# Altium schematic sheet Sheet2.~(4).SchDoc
size A3
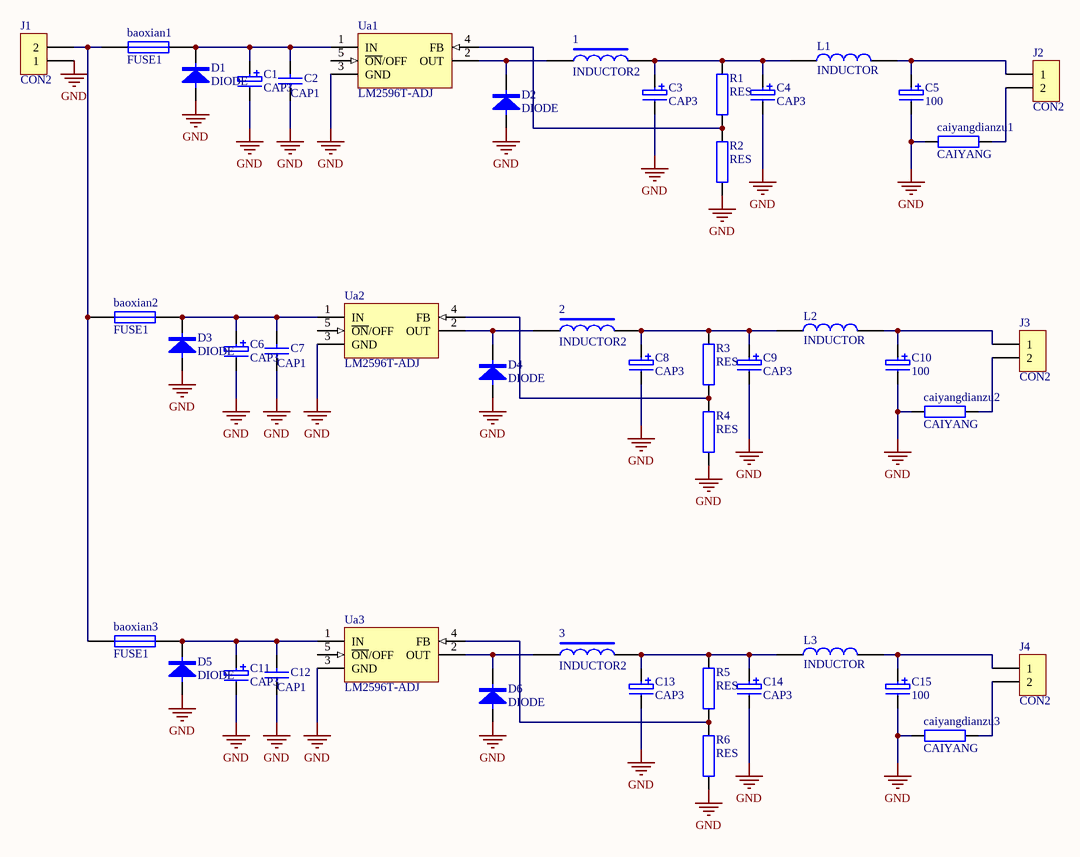
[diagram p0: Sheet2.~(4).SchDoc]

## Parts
1  INDUCTOR2
2  INDUCTOR2
3  INDUCTOR2
baoxian1  FUSE1  [RAD0.5]
baoxian2  FUSE1  [RAD0.5]
baoxian3  FUSE1  [RAD0.5]
C1  CAP3  [RB2]
C2  CAP1  [RAD0.2]
C3  CAP3  [RB3]
C4  CAP3  [RB3]
C5  100  [RB1]
C6  CAP3  [RB2]
C7  CAP1  [RAD0.2]
C8  CAP3  [RB3]
C9  CAP3  [RB3]
C10  100  [RB1]
C11  CAP3  [RB2]
C12  CAP1  [RAD0.2]
C13  CAP3  [RB3]
C14  CAP3  [RB3]
C15  100  [RB1]
caiyangdianzu1  CAIYANG  [AXIAL0.8]
caiyangdianzu2  CAIYANG  [AXIAL0.8]
caiyangdianzu3  CAIYANG  [AXIAL0.8]
D1  DIODE  [DIODE0.4]
D2  DIODE  [DIODE0.2]
D3  DIODE  [DIODE0.4]
D4  DIODE  [DIODE0.2]
D5  DIODE  [DIODE0.4]
D6  DIODE  [DIODE0.2]
J1  CON2  [BCON2]
J2  CON2  [BCON2]
J3  CON2  [BCON2]
J4  CON2  [BCON2]
L1  INDUCTOR  [LHF440]
L2  INDUCTOR  [LHF440]
L3  INDUCTOR  [LHF440]
R1  RES  [AXIAL0.3]
R2  RES  [AXIAL0.3]
R3  RES  [AXIAL0.3]
R4  RES  [AXIAL0.3]
R5  RES  [AXIAL0.3]
R6  RES  [AXIAL0.3]
Ua1  LM2596T-ADJ  [SIP-5]
Ua2  LM2596T-ADJ  [SIP-5]
Ua3  LM2596T-ADJ  [SIP-5]

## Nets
GND: C1.2 C2.2 C3.2 C4.2 C5.2 C6.2 C7.2 C8.2 C9.2 C10.2 C11.2 C12.2 C13.2 C14.2 C15.2 caiyangdianzu1.2 caiyangdianzu2.2 caiyangdianzu3.2 D1.1 D2.1 D3.1 D4.1 D5.1 D6.1 J1.1 R2.1 R4.1 R6.1 Ua1.3(GND) Ua2.3(GND) Ua3.3(GND)
Net1_1: 1.1 D2.2 Ua1.2(OUT)
Net1_2: 1.2 C3.1 C4.1 L1.1 R1.2
Net2_1: 2.1 D4.2 Ua2.2(OUT)
Net2_2: 2.2 C8.1 C9.1 L2.1 R3.2
Net3_1: 3.1 D6.2 Ua3.2(OUT)
Net3_2: 3.2 C13.1 C14.1 L3.1 R5.2
Netbaoxian1_1: baoxian1.1 C1.1 C2.1 D1.2 Ua1.1(IN)
Netbaoxian1_2: baoxian1.2 baoxian2.2 baoxian3.2 J1.2
Netbaoxian2_1: baoxian2.1 C6.1 C7.1 D3.2 Ua2.1(IN)
Netbaoxian3_1: baoxian3.1 C11.1 C12.1 D5.2 Ua3.1(IN)
NetC5_1: C5.1 J2.1 L1.2
NetC10_1: C10.1 J3.1 L2.2
NetC15_1: C15.1 J4.1 L3.2
Netcaiyangdianzu1_1: caiyangdianzu1.1 J2.2
Netcaiyangdianzu2_1: caiyangdianzu2.1 J3.2
Netcaiyangdianzu3_1: caiyangdianzu3.1 J4.2
NetR1_1: R1.1 R2.2 Ua1.4(FB)
NetR3_1: R3.1 R4.2 Ua2.4(FB)
NetR5_1: R5.1 R6.2 Ua3.4(FB)

Not connected (* = marked no-connect by the designer): Ua1 5(~{ON}/OFF); Ua2 5(~{ON}/OFF); Ua3 5(~{ON}/OFF)

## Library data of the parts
baoxian1-baoxian3 = FUSE1: Fuse
C5 C10 C15 = CAP3
caiyangdianzu1-caiyangdianzu3 = RES
J1-J4 = CON2: Connector
Ua1-Ua3 = LM2596T-5.0: Simple Switcher Power Converter 150 kHz 3A Step Down Voltage Regulator; PackageDocument: 2000; Note: Tab is connected to GND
